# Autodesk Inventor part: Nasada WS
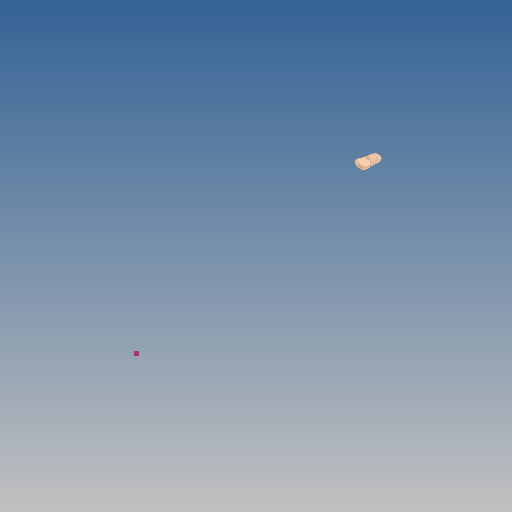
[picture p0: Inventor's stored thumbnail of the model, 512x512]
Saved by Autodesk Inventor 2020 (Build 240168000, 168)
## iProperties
Created: 2019-10
Part Number: Nasada WS
Material: GFRP
Document SubType Name: Modeling
Designer: yello
Density: 1.75 g/cm^3
Appearance: Default
Author: yello
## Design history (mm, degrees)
feature "Nasada WS"
sketch "Sketch1"
  geometry: 1 further point
  constraints: 1 other
body "Solid1"
